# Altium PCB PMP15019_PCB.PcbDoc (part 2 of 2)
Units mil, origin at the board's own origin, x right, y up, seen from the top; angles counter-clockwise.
Board outline 3000 x 2000 mil, 6 copper layers (Top Layer, Signal Layer 1, Signal Layer 2, Signal Layer 3, Signal Layer 4, Bottom Layer), stack 61.6 mil thick; 82 components, 32 nets, 164 pads, 220 vias.
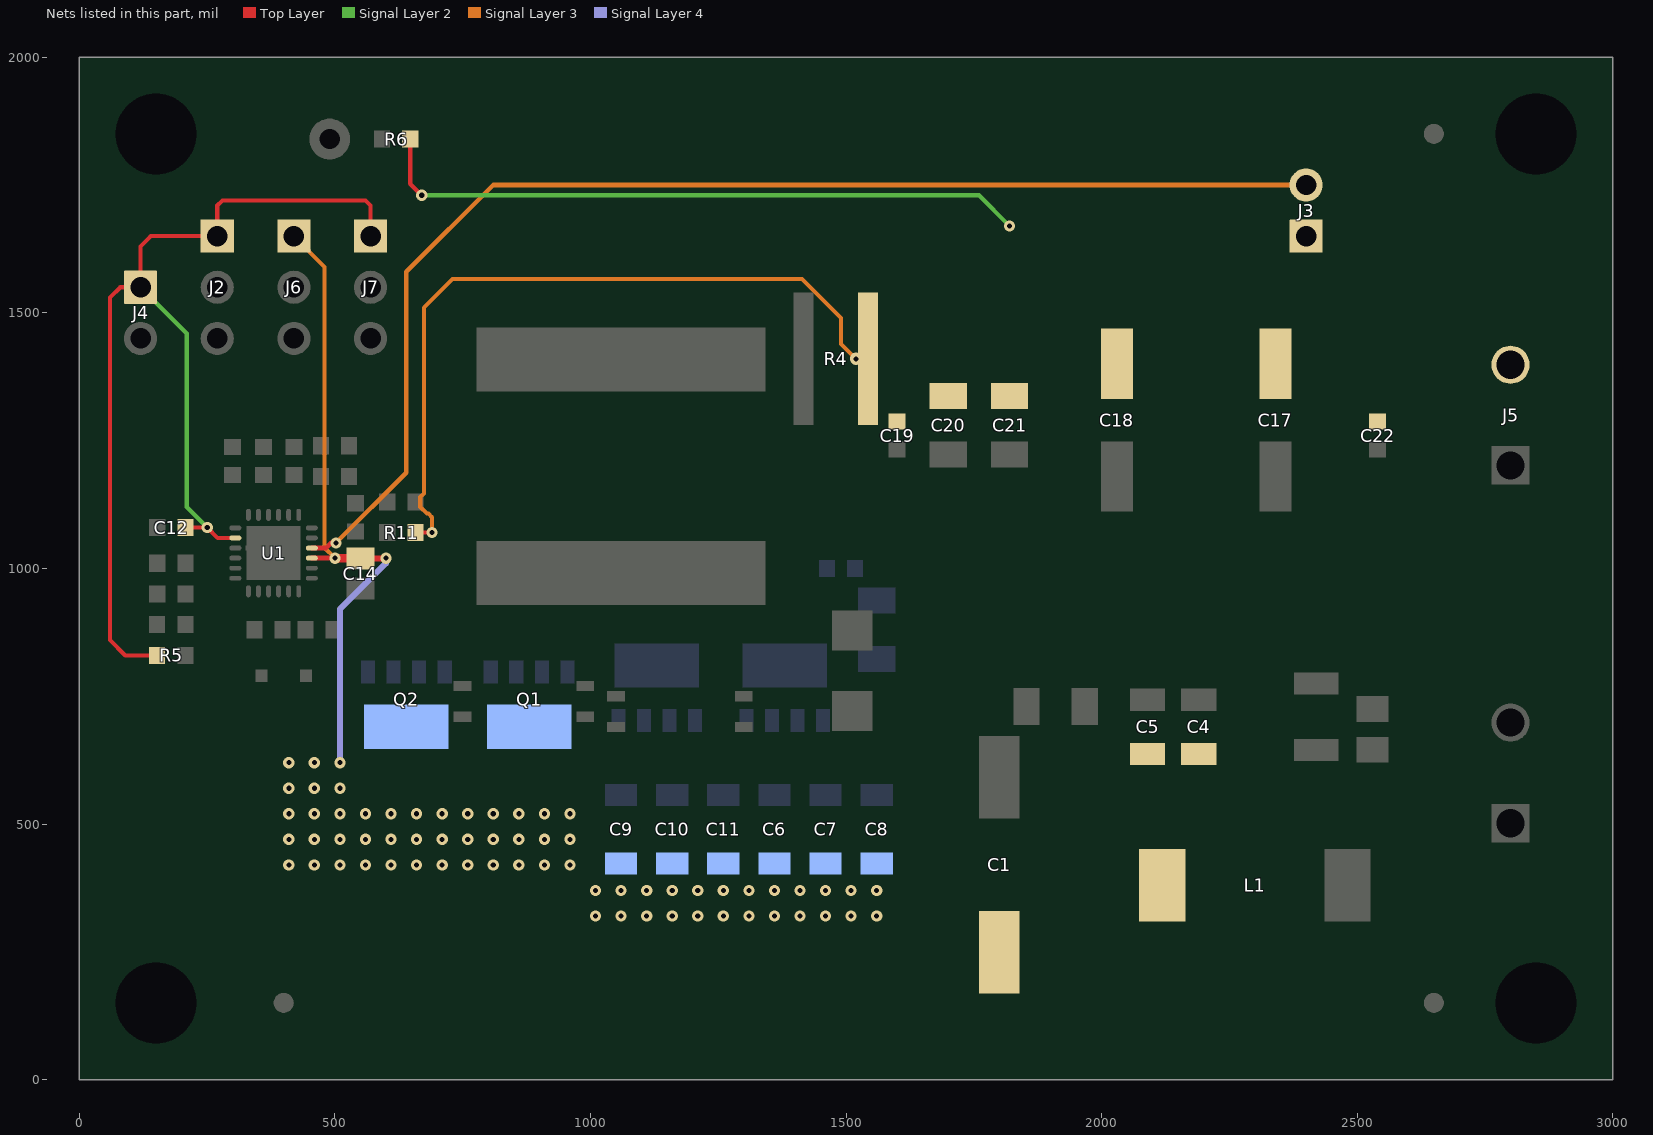
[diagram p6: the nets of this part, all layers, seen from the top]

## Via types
v1: diameter 22, hole 10, Top Layer to Bottom Layer, tented both sides, 199 vias
v2: diameter 22, hole 10, Top Layer to Bottom Layer, 14 vias
v3: diameter 19.68, hole 7.87, Top Layer to Bottom Layer, 5 vias
v4: diameter 24, hole 10, Top Layer to Bottom Layer, tented both sides, 2 vias

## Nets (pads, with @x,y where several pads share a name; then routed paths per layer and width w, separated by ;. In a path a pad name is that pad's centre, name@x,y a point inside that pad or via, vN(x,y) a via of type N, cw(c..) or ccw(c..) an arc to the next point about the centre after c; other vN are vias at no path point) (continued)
VCCX: J3.2 U1.16 | length 2469.2
  Top Layer w9: U1.16@454.96,1039.84 483.16,1039.84 493.31,1050 500.16,1050 500.28,1049.87 v2(502.38,1049.87)
  Signal Layer 3 w9: v2(502.38,1049.87) 640,1187.49 640,1580 810,1750 J3.2@2400,1750
VDDA: C12.2 J2.1 J4.1 J7.1 R5.1 U1.2 | length 2133.6
  Top Layer w8: J4.1@110,1560 120,1570 120,1630 140,1650 J2.1@270,1650 270,1710 280,1720 560,1720 570,1710 J7.1@570,1650 ; J4.1@120,1550 80.32,1550 60.32,1530 60.32,859.68 90,830 R5.1@152.44,830 ; C12.2@207.72,1080 v2(250.47,1080) 270.94,1059.53 U1.2@305.35,1059.53
  Signal Layer 2 w8: J4.1@120,1550 210.32,1459.68 210.32,1120.16 v2(250.47,1080)
VIN: C1.1 C4.1 C5.1 C6.1 C7.1 C8.1 C9.1 C10.1 C11.1 C14.2 J6.1 L1.2 Q1.5 Q2.5 U1.15 | length 1245.6
  Top Layer w10: U1.15@454.96,1020.16 v2@500,1020.16
  Top Layer w12: C14.2@550.16,1019.53 599.53,1019.53 v1(600,1020)
  Top Layer w16: v2(500.16,1020) C14.2@549.68,1020
  Signal Layer 3 w8: J6.1@420,1650 480,1590 480,1060.34 479.51,1059.84 479.51,1040.4 499.91,1020 v2(500.16,1020)
  Signal Layer 4 w12: v1(510,620) 510,920 600,1010 v1(600,1020)
  other v1: 1010,320 1060,320 1110,320 1160,320 1210,320 1260,320 1310,320 1360,320 1410,320 1460,320 1510,320 1560,320 1010,370 1060,370 1110,370 1160,370 1210,370 1260,370 1310,370 1360,370 1410,370 1460,370 1510,370 1560,370 410,420 460,420 510,420 560,420 610,420 660,420 710,420 760,420 810,420 860,420 910,420 960,420 410,470 460,470 510,470 560,470 610,470 660,470 710,470 760,470 810,470 860,470 910,470 960,470 410,520 460,520 510,520 560,520 610,520 660,520 710,520 760,520 810,520 860,520 910,520 960,520 410,570 460,570 510,570 410,620 460,620
VOUT: C17.1 C18.1 C19.1 C20.1 C21.1 C22.1 J3.1 J5.2 R4.2 R6.1 R11.2 | length 2742.8
  Top Layer w8: R6.1@647.56,1840 647.56,1752.44 v1(670,1730) ; R11.2@657.72,1070 v1(690,1070)
  Signal Layer 2 w8: v1(670,1730) 1760,1730 v1(1820,1670)
  Signal Layer 3 w8: v1(690,1070) 690,1100 682.87,1107.13 680.53,1107.13 667.13,1120.53 667.13,1139.47 668.13,1140.47 668.13,1140.75 674.13,1146.75 674.13,1510 730,1565.87 1414.13,1565.87 1490,1490 1490,1439.39 v4(1519.39,1410)
pads on no net: FID1.1 FID2.1 FID3.1 MH1.1 MH2.1 MH3.1 MH4.1

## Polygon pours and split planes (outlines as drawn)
AGND on Top Layer "Top Layer-No Net" (solid, pour order 174): 250.16,860 70.32,860 70.31,1490 650.32,1490 650.31,1139.76 250.16,1139.76
NetC2_1 on Top Layer "Top Layer-NetC2-1" (solid, pour order 172): 2932.8,302.8 2690,302.8 2570,182.8 2350,182.8 2350,645.12 2377.69,672.8 2600,672.8 2670,602.8 2680,592.8 2927.2,592.8 2980,540 2980,350
VIN on Top Layer "Top Layer-VIN" (solid, pour order 177): 2210,160 520,160 480,200 480,270 450,300 70,300 50,320 50,720 70,740 950.03,740 980,710.03 980,540 1015.43,504.57 1890.79,504.57 1911.18,524.96 1911.18,670 2076.61,670 2220,670 2260,630 2260,210
NetL2_2 on Top Layer "Top Layer-Net L2-2" (solid, pour order 173): 1450,1280 770,1280 770,1680 1450,1680
VOUT on Top Layer "Top Layer-Vout" (solid, pour order 176): 2992.3,1340 2717.32,1340 2700,1340 2630,1270 1510,1270 1510,1690 2996.38,1690
PGND on Top Layer "Top Layer-PGND" (solid, pour order 178): 3000,0 10,0 0,10 0,2000 3000,2000
NetC15_2 on Top Layer "Top Layer-C12-2" (solid, pour order 175): 541.57,770 540,771.57 540,850 650,960 695.58,960 752.91,1017.33 752.91,1062.91 790,1100 1390.49,1099.54 1410,1080 1480,1010 1480,770
VIN on Bottom Layer "Bottom Layer-Vin" (solid, pour order 188): 80,740 958.35,740 977.44,720.92 977.44,539.38 1012.25,504.57 1575.43,504.57 1599.37,480.63 1599.37,209.37 1570,180 350,180 320,210 320,270 290,300 80,300 50,330 50,710
NetC15_2 on Bottom Layer "Bottom Layer-C12-2" (solid, pour order 187): 541.57,770 540,771.57 540,850 650,960 700,960 752.91,1012.91 752.91,1062.91 790,1100 1390,1100 1480,1010 1480,770
PGND on Bottom Layer "Bottom Layer-PGND" (solid, pour order 189): 0,0 0,2000 3000,2000 3000,0
PGND on Signal Layer 1 "Signal Layer 1-PGND" (solid, pour order 179): 0,0 0,2000 3000,2000 3000,0
PGND on Signal Layer 4 "Signal Layer4 -PGND" (solid, pour order 186): 0,0 0,2000 3000,2000 3000,0
VIN on Signal Layer 2 "Bottom Layer-Vin" (solid, pour order 181): 90,640 941.81,640 977.44,604.38 977.44,542.56 1015.43,504.57 1578.74,504.57 1599.37,483.94 1599.37,209.37 1570,180 350,180 320,210 320,270 290,300 80,300 50,330 50,600
NetC15_2 on Signal Layer 2 "Top Layer-C12-2" (solid, pour order 180): 560,800 560,868.61 650.24,958.86 695.82,958.86 753.16,1016.19 753.16,1061.77 790.24,1098.86 1390.73,1098.39 1410.24,1078.86 1480.24,1008.86 1480.24,789.09 570.91,789.09
PGND on Signal Layer 2 "Top Layer-No Net1" (solid, pour order 182): 0,0 0,2000 3000,2000 3000,0
VIN on Signal Layer 3 "Bottom Layer-Vin" (solid, pour order 184): 70,640 943.78,640 977.44,606.34 977.44,524.96 997.83,504.57 1565.43,504.57 1599.37,470.63 1599.37,209.37 1570,180 345.85,180 320,205.85 320,279.61 299.61,300 70,300 50,320 50,620
NetC15_2 on Signal Layer 3 "Top Layer-C12-2" (solid, pour order 183): 565,795 565,870.58 654.42,960 700,960 757.33,1017.33 757.33,1062.91 794.42,1100 1394.9,1099.54 1414.42,1080 1484.42,1010 1484.42,770 590,770
PGND on Signal Layer 3 "Top Layer-No Net2" (solid, pour order 185): 0,0 0,2000 3000,2000 3000,0

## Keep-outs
Keep-Out Layer:
  the board outline again, w7
  text ".Layer_Name" at 577,-858.49 h60

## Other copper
Top Layer:
  rectangle net NetC15_2: 1462.67,835.59 1560,927.22
  pour cut-out: 1457.21,1270 1457.21,1690 1499.8,1690 1499.8,1270
  pour cut-out: 3000,940 2670,940 2670,970 3000,970
  pour cut-out: 2240,700 2364.88,700 2364.88,581.82 2430,516.71 2430,200 2480,150 2120,150 2170,200 2170,506.13 2240,576.13
  pour cut-out: 1367.09,1270 1367.09,1110 785.58,1110 752.91,1077.33 752.91,1270
  pour cut-out: 2240,660 1849.37,660 1849.37,690 2220,690 2240,690 2240,670
  pour cut-out: 1900.99,514.76 1849.37,514.76 1849.37,660 1930,660 1900,630
  pour cut-out: 2932.8,278.33 2998.33,278.33 ccw(c2998.33,280) 3000,280 3000,350
  pour cut-out: 2927.2,617.28 2994.44,617.28 ccw(c2994.44,619.68) 2996.85,619.68 2996.85,550
  text ".Layer_Name" at 577,-858.49 h60
Signal Layer 1:
  pour cut-out: 2077.56,639.13 3000,639.13 3000,260 2720,260 2580,120 2077.56,120
  pour cut-out: 2860,698.47 cw(c2804.66,693.82) 2809.32,638.47 2789.32,638.47 cw(c2794.66,693.13) 2740,698.47 cw(c2794.66,703.82) 2789.32,758.47 2809.32,758.47 cw(c2804.66,703.13)
  text ".Layer_Name" at 577,-858.49 h60
Signal Layer 2:
  pour cut-out: 2077.56,640 3000,640 3000,260 2710,260 2570,120 2077.56,120
  pour cut-out: 2860,698.47 cw(c2804.66,693.82) 2809.32,638.47 2789.32,638.47 cw(c2795.87,694.61) 2739.74,701.17 cw(c2793.18,705.03) 2789.32,758.47 2809.32,758.47 cw(c2804.66,703.13)
  text ".Layer_Name" at 577,-858.49 h60
Signal Layer 3:
  pour cut-out: 2080,650 3000,650 3000,260 2720,260 2580,120 2080,120
  pour cut-out: 2860,698.47 cw(c2804.66,693.82) 2809.32,638.47 2789.32,638.47 cw(c2794.38,693.41) 2739.45,698.47 cw(c2794.38,703.54) 2789.32,758.47 2809.32,758.47 cw(c2804.66,703.13)
  text ".Layer_Name" at 577,-858.49 h60
Signal Layer 4:
  pour cut-out: 2077.56,650 3000,650 3000,260 2710,260 2570,120 2077.56,120
  pour cut-out: 2860,698.47 cw(c2804.66,693.82) 2809.32,638.47 2789.32,638.47 cw(c2794.36,693.43) 2739.41,698.47 cw(c2794.36,703.52) 2789.32,758.47 2809.32,758.47 cw(c2804.66,703.13)
  text ".Layer_Name" at 577,-858.49 h60
Bottom Layer:
  pour cut-out: 2080,650 3000,650 3000,264.21 2714.2,264.21 2570,120 2080,120
  pour cut-out: 2860,698.47 cw(c2804.66,693.82) 2809.32,638.47 2789.32,638.47 cw(c2794.66,693.13) 2740,698.47 cw(c2794.66,703.82) 2789.32,758.47 2809.32,758.47 cw(c2804.66,703.13)
  text ".Layer_Name" at 577,-858.49 h60

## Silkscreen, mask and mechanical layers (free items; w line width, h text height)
Top Overlay:
  region: 2540,150 2240,150 2240,50 2540,50
  lines w7: 290,800 340,850 ; 566.93,1156.93 576.85,1156.93 566.89,1166.89 566.89,1156.89 590,1180 590,1210 620,1240 ; 340,850 340,840 330,850 340,850
  text "+" at 2940,1560 h100 r90
  text "VOUT" at 2570,1480 h60 r90
  text "-" at 2940,1010 h100 r90
  text "-" at 2940,830 h100 r90
  text "+" at 2940,320 h100 r90
  text "VIN" at 2630,230 h60 r90
  text ".PRJ_Number" at 1550,70 h60
  text ".PCB_Rev" at 2060,70.01 h60
  text "-" at 2170,70.01 h60
  text ".Layer_Name" at 577,-858.49 h60
Bottom Overlay:
  text ".Layer_Name" at 577,-858.49 h60
Top Paste:
  text ".Layer_Name" at 577,-858.49 h60
Bottom Paste:
  text ".Layer_Name" at 577,-858.49 h60
Top Solder:
  text ".Layer_Name" at 577,-858.49 h60
  text ".Layer_Name" at 577,-858.49 h60
Bottom Solder:
  text ".Layer_Name" at 577,-858.49 h60
Drill Guide:
  text ".Layer_Name" at 577,-858.49 h60
M1 Board Outline:
  the board outline again, w10
  text ".Layer_Name" at 577,-858.49 h60
M2 Board Dimensions:
  rectangle: 125,-400 500,-275
  rectangle: 0,-275 125,-150
  lines w7: 0,-275 1000,-275 ; 125,-400 125,-150 ; 250,-400 250,-150 ; 500,-400 500,-150 ; 750,-400 750,-150 ; 0,-400 0,-150 1000,-150 1000,-400 0,-400
  text ".Layer_Name" at 577,-858.49 h60
M3 3D STEP Top:
  text ".Layer_Name" at 577,-858.49 h60
M4 3D STEP Bottom:
  text ".Layer_Name" at 577,-858.49 h60
M5 Assembly Top:
  lines w10: -292,-930.17 6308,-930.17 ; -292,-726.83 6310,-726.83 ; -292,-523.5 -292,-1133.5 3713,-1133.5 6310,-1133.5 6310,-523.5 -291.5,-523.5 -291.5,-1133.5 1284,-1133.5 ; 2173,-1133.5 2173,-523.5 ; 3440,-726.83 3440,-523.5 ; 4280,-726.83 4280,-523.5 ; 4902,-1140 4902,-937.17
  text "COMPONENTS MARKED 'DNP' SHOULD NOT BE POPULATED." at 1153.5,-318.5 h60
  text "ASSEMBLY VARIANT:" at 1153,-434 h60
  text ".VariantName" at 2189,-434 h60
  text "PCB VIEWED FROM TOP SIDE" at -228.5,-655.67 h60
  text "BOARD #:" at 2248,-655.67 h60
  text ".PRJ_Number" at 2793.5,-655.67 h60
  text "REV:" at 3638,-655.67 h60
  text ".PCB_Rev" at 3929.5,-655.67 h60
  text "SVN REV:" at 4476,-655.67 h60
  text ".VersionControl_RevNumber" at 4982,-655.67 h60
  text "TID #:" at 2248,-859 h60
  text ".TID" at 2793.5,-859 h60
  text "PLOT NAME =" at -228.5,-1064.34 h60
  text ".plot_File_Name" at 577,-1064.34 h60
  text "GENERATED    :" at 2250,-1064.34 h60
  text ".Print_Date" at 3119.5,-1064.34 h60
  text ".Print_Time" at 3848.5,-1064.34 h60
  text "TEXAS INSTRUMENTS" at 5113,-1064.34 h60
M6 Assembly Bottom:
  lines w10: -292.5,-727.33 6309.5,-727.33 ; -290.5,-930.67 6309.5,-930.67 ; 1115.5,-1140.5 1115.5,-937.67 ; 1737.5,-727.33 1737.5,-524 ; 2577.5,-727.33 2577.5,-524 ; 3844.5,-1134 3844.5,-524 ; 4733.5,-1134 6309,-1134 6309,-524 -292.5,-524 -292.5,-1134 2304.5,-1134 6309.5,-1134 6309.5,-524
  text "COMPONENTS MARKED 'DNP' SHOULD NOT BE POPULATED." at 6102,-318 h60
  text ".VariantName" at 5058,-434 h60
  text "ASSEMBLY VARIANT:" at 6097,-434 h60
  text ".VersionControl_RevNumber" at 1035.5,-656.17 h60
  text "SVN REV:" at 1541.5,-656.17 h60
  text ".PCB_Rev" at 2088,-656.17 h60
  text "REV:" at 2379.5,-656.17 h60
  text ".PRJ_Number" at 3224,-656.17 h60
  text "BOARD #:" at 3769.5,-656.17 h60
  text "PCB VIEWED FROM BOTTOM SIDE" at 6246,-656.17 h60
  text ".TID" at 3224,-859.5 h60
  text "TID #:" at 3769.5,-859.5 h60
  text "TEXAS INSTRUMENTS" at 904.5,-1064.84 h60
  text ".Print_Time" at 2169,-1064.84 h60
  text ".Print_Date" at 2898,-1064.84 h60
  text "GENERATED    :" at 3767.5,-1064.84 h60
  text ".plot_File_Name" at 5440.5,-1064.84 h60
  text "PLOT NAME =" at 6246,-1064.84 h60
M9 Title Sheet:
  drawing of 57 lines, arcs and shapes, not listed
  text "1" at 739.84,8036.5 h70
  text "2" at 3235.5,8036.5 h70
  text "3" at 5724.84,8036.5 h70
  text "4" at 8231.51,8036.5 h70
  text "5" at 10730.5,8036.5 h70
  text "6" at 13235.5,8036.5 h70
  text "A" at -416.5,6893.5 h70
  text "A" at 14383.5,6893.5 h70
  text "B" at -416.5,4513.5 h70
  text "B" at 14383.5,4513.5 h70
  text "C" at -416.5,2138.5 h70
  text "C" at 14383.5,2138.5 h70
  text "PROJECT TITLE:" at 11343.5,277.5 h45
  text ".PRJ_Title" at 11393.5,144.17 h70
  text "DESIGNED FOR:" at 11343.5,-23.5 h45
  text ".PRJ_Customer" at 11393.5,-163.5 h70
  text "D" at -416.5,-231.5 h70
  text "D" at 14383.5,-231.5 h70
  text "FILE NAME:" at 11343.5,-323.5 h45
  text ".PCB_File_Name_No_Path" at 11393.5,-443.5 h70
  text "Texas Instruments (TI) and/or its licensors do not warrant the accuracy or completeness of this specification" at 6374,-605.34 h45
  text "ENGINEER:" at 11343.5,-613.5 h45
  text "LAYOUT BY:" at 12848.5,-613.5 h45
  text "or any information contained therein. TI and/or its licensors do not warrant that this design will meet" at 6329.01,-718 h45
  text ".PRJ_Engineer" at 11393.5,-768.49 h70
  text ".PCB_Layout" at 12899,-768.49 h70
  text "the specifications, will be suitable for your application or fit for any particular purpose, or will operate in" at 6329.01,-830.67 h45
  text ".Layer_Name" at 577,-858.49 h60
  text "ALTIUM DESIGNER VERSION:" at 12848.5,-923.5 h45
  text "an implementation. TI and/or its licensors do not warrant that the design is production worthy. You should" at 6329.01,-943.33 h45
  text "completely validate and test your design implementation to confirm the system functionality for your application." at 6374,-1056 h45
  text ".print_Scale" at 11393.5,-1056.83 h70
  text ".Application_BuildNumber" at 12899,-1056.83 h70
  text "1" at 739.84,-1263.5 h70
  text "2" at 3235.5,-1263.5 h70
  text "3" at 5724.84,-1263.5 h70
  text "4" at 8231.51,-1263.5 h70
  text "5" at 10730.5,-1263.5 h70
  text "6" at 13235.5,-1263.5 h70
M10 Fab Notes:
  drawing of 173 lines, arcs and shapes, not listed
  text "DESIGN INFORMATION" at 12377.02,6201 h60
  text "MIN. TRACK WIDTH:" at 11732.46,6021 h60
  text "8" at 12828.7,6021 h60
  text "MIL" at 12983.46,6021 h60
  text "MIN. CLEARANCE:" at 11732.46,5889 h60
  text "0.2" at 12768.7,5889 h60
  text "mm" at 12983.46,5889 h60
  text "MIN. VIA PAD SIZE:" at 11732.46,5757 h60
  text "24" at 12798.71,5757 h60
  text "MIL" at 12983.46,5757 h60
  text "0.05mm (2MIL)" at 12427.46,5615.29 h60
  text "MINIMUM ANNULAR RING" at 11403.23,5611 h60
  text "EXTERNAL" at 13135.46,5611 h60
  text "PER" at 11603.23,5493 h60
  text "IPC-D-275 CLASS 2 LEVEL C" at 11823.23,5493 h60
  text "MIL, HOLES" at 13311.46,5380.71 h60
  text "+/-" at 12919,5380 h60
  text "+/-" at 13773,5380 h60
  text "REGISTRATION TOLERANCES:" at 11403.23,5375 h60
  text "METAL" at 12603,5375 h60
  text "5" at 13179.2,5375 h60
  text "3" at 14012.2,5375 h60
  text "MIL" at 14128.46,5375 h60
  text "+/-" at 13773,5262 h60
  text "HOLE SIZE TOLERANCE (UNLESS OTHERWISE SPECIFIED):" at 11403.23,5257 h60
  text "3" at 14012.2,5257 h60
  text "MIL" at 14128.46,5257 h60
  text "MATERIAL:" at 11328.46,5047.54 h60
  text "FR-4 High Tg" at 12314.9,4907.21 h60
  text "FR-408" at 11749.46,4898.64 h60
  text "OTHER" at 13237.46,4898.64 h60
  text "X" at 12160,4895 h60
  text "62 MIL (1.6mm) +/-10%" at 12069.56,4735.92 h60
  text "THICKNESS:" at 11403.23,4731.64 h60
  text "X" at 11941.4,4731.64 h60
  text "OTHER" at 13354.46,4731.64 h60
  text "TOLERANCE:" at 11403.23,4573.64 h60
  text "X" at 12242.53,4573.64 h60
  text "ANSI IPC-6012 TYPE 3 CLASS 2" at 12429.48,4573.64 h60
  text "OTHER +/-" at 12429.46,4417.64 h60
  text "BOW & TWIST:" at 11403.23,4260.64 h60
  text "X" at 12242.53,4260.64 h60
  text "ANSI IPC-6012 TYPE 3 CLASS 2" at 12429.48,4260.64 h60
  text "OTHER +/-" at 12429.46,4102.13 h60
  text "DRILLING:" at 11328.46,3963.64 h60
  text "REFERENCE:" at 11403.23,3846.64 h60
  text "X" at 12051.46,3846.64 h60
  text "AS SHOWN" at 12238.46,3846.64 h60
  text "X" at 12952.46,3846.64 h60
  text "NC_DRILL FILES" at 13089.46,3846.64 h60
  text "PTH COPPER THICKNESS:" at 11403.23,3688.64 h60
  text "X" at 12533.46,3688.64 h60
  text "20-30 um" at 12670.46,3688.64 h60
  text "OTHER" at 13387.46,3688.64 h60
  text "BOARD FINISH:" at 11328.46,3529.64 h60
  text "SILKSCREEN:" at 11483.68,3411.64 h60
  text "X" at 12432.46,3411.64 h60
  text "TOP" at 12558.46,3411.64 h60
  text "X" at 12942.46,3411.64 h60
  text "BOTTOM" at 13069.46,3411.64 h60
  text "SILKSCREEN COLOR:" at 11483.68,3244.64 h60
  text "X" at 12431.42,3244.64 h60
  text "WHITE" at 12558.46,3244.64 h60
  text "OTHER" at 13069.46,3244.64 h60
  text "X" at 12562.42,3085.44 h60
  text "GREEN" at 12689.46,3085.44 h60
  text "OTHER" at 13307.46,3085.44 h60
  text "SOLDER RESIST COLOR:" at 11483.68,3074.64 h60
  text "X" at 12562.42,2915.44 h60
  text "MATTE" at 12689.46,2915.44 h60
  text "SEMI-GLOSS" at 13307,2914.8 h60
  text "IMMERSION GOLD (ENIG)" at 12389.46,2726.92 h60
  text "ENEPIG" at 13727,2723.64 h60
  text "SURFACE FINISH:" at 11328.46,2722.64 h60
  text "X" at 12202.51,2722.64 h60
  text "IMM. TIN/SILVER OR EQUIV" at 11658,2565.64 h60
  text "OTHER" at 13089.46,2565.64 h60
  text "X" at 12200,2390 h60
  text "ARRAY/PANEL:" at 11328.46,2386.64 h60
  text "CUT AND TRIM PER M1 BOARD OUTLINE" at 12389.46,2382.35 h60
  text "N.C. ROUTE" at 12389.46,2230.64 h60
  text "V. SCORE" at 13255.46,2230.64 h60
  text "CERTIFICATION:" at 11328.46,2093.64 h60
  text "MATERIALS AND WORKMANSHIP FOR ALL PCBS" at 12053.46,2093.64 h60
  text "TO MEET OR EXCEED THE REQUIREMENTS OF:" at 12053.46,1995.64 h60
  text "X" at 11679.96,1859.13 h60
  text "ANSI IPC-A-600F CLASS ->" at 11818.96,1859.13 h60
  text "X" at 13458.02,1859.13 h60
  text "2" at 13576.96,1859.14 h60
  text "1" at 13261.96,1857.64 h60
  text "3" at 13930.96,1857.64 h60
  text "X" at 12494.02,1699.64 h60
  text "RoHS" at 12630.96,1699.64 h60
  text "OTHER" at 13275.36,1699.64 h60
  text "PER ORDER" at 13672.42,1699.64 h60
  text "ALL BOARDS MUST MEET OR EXCEED UL94-V0 REQUIREMENTS." at 11356,1534 h60
  text "PCB MUST BEAR THE UL94V-0 UL REGISTERED MATERIAL ID NUMBER" at 11356,1414 h60
  text "ADDITIONAL REQUIREMENTS:" at 11328.46,1240.64 h60
  text "MICROSECTION:" at 11403.23,1125.64 h60
  text "YES" at 12308.96,1125.64 h60
  text "REQUIRED" at 13170.46,969.49 h60
  text "BARE BOARD ELEC. TEST:" at 11403.23,966.64 h60
  text "NONE" at 12708.96,966.64 h60
  text "X" at 13043.46,966.64 h60
  text "PER ORDER" at 13762.46,966.64 h60
  text ".Layer_Name" at 577,-858.49 h60
M11 Gerber Information:
  lines w10: -292,-930.17 6308,-930.17 ; -292,-726.83 6310,-726.83 ; -292,-523.5 -292,-1133.5 3713,-1133.5 6310,-1133.5 6310,-523.5 -291.5,-523.5 -291.5,-1133.5 1284,-1133.5 ; 2173,-1133.5 2173,-523.5 ; 3440,-726.83 3440,-523.5 ; 4280,-726.83 4280,-523.5 ; 4902,-1140 4902,-937.17
  text "ALL ARTWORK VIEWED FROM TOP SIDE" at -228.5,-655.67 h60
  text "BOARD #:" at 2248,-655.67 h60
  text ".PRJ_Number" at 2793.5,-655.67 h60
  text "REV:" at 3638,-655.67 h60
  text ".PCB_Rev" at 3929.5,-655.67 h60
  text "SVN REV:" at 4476,-655.67 h60
  text ".VersionControl_RevNumber" at 4982,-655.67 h60
  text "LAYER NAME =" at -228.5,-858.49 h60
  text "TID #:" at 2248,-859 h60
  text ".TID" at 2793.5,-859 h60
  text "PLOT NAME =" at -228.5,-1064.34 h60
  text ".plot_File_Name" at 577,-1064.34 h60
  text "GENERATED    :" at 2250,-1064.34 h60
  text ".Print_Date" at 3119.5,-1064.34 h60
  text ".Print_Time" at 3848.5,-1064.34 h60
  text "TEXAS INSTRUMENTS" at 5113,-1064.34 h60
M12 Stackup:
  drawing of 399 lines, arcs and shapes, not listed
  text "Layer" at 6790.74,7870 h60
  text "Name" at 7200.66,7870 h60
  text "Material" at 8140.4,7870 h60
  text "Thickness" at 9000.16,7870 h60
  text "Constant" at 9650,7870 h60
  text "Board Layer Stack" at 10219.86,7870 h60
  text "1" at 6790.74,7750 h60
  text "Top Overlay" at 7200.66,7750 h60
  text "2" at 6790.74,7630 h60
  text "Top Solder" at 7200.66,7630 h60
  text "Solder Resist" at 8140.4,7630 h60
  text "0.40mil" at 9000.16,7630 h60
  text "3.5" at 9650,7630 h60
  text "3" at 6790.74,7510 h60
  text "Top Layer" at 7200.66,7510 h60
  text "Copper" at 8140.4,7510 h60
  text "4.20mil" at 9000.16,7510 h60
  text "4" at 6790.74,7390 h60
  text "Dielectric1" at 7200.66,7390 h60
  text "FR-4" at 8140.4,7390 h60
  text "5.00mil" at 9000.16,7390 h60
  text "4.8" at 9650,7390 h60
  text "5" at 6790.74,7270 h60
  text "Signal Layer 1" at 7200.66,7270 h60
  text "Copper" at 8140.4,7270 h60
  text "2.80mil" at 9000.16,7270 h60
  text "6" at 6790.74,7150 h60
  text "Dielectric 3" at 7200.66,7150 h60
  text "5.00mil" at 9000.16,7150 h60
  text "4.2" at 9650,7150 h60
  text "7" at 6790.74,7030 h60
  text "Signal Layer 2" at 7200.66,7030 h60
  text "Copper" at 8140.4,7030 h60
  text "2.80mil" at 9000.16,7030 h60
  text "8" at 6790.74,6910 h60
  text "Dielectric 4" at 7200.66,6910 h60
  text "22.00mil" at 9000.16,6910 h60
  text "4.2" at 9650,6910 h60
  text "9" at 6790.74,6790 h60
  text "Signal Layer 3" at 7200.66,6790 h60
  text "Copper" at 8140.4,6790 h60
  text "2.80mil" at 9000.16,6790 h60
  text "10" at 6790.74,6670 h60
  text "Dielectric 5" at 7200.66,6670 h60
  text "5.00mil" at 9000.16,6670 h60
  text "4.2" at 9650,6670 h60
  text "11" at 6790.74,6550 h60
  text "Signal Layer 4" at 7200.66,6550 h60
  text "Copper" at 8140.4,6550 h60
  text "2.80mil" at 9000.16,6550 h60
  text "12" at 6790.74,6430 h60
  text "Dielectric 2" at 7200.66,6430 h60
  text "5.00mil" at 9000.16,6430 h60
  text "4.2" at 9650,6430 h60
  text "13" at 6790.74,6310 h60
  text "Bottom Layer" at 7200.66,6310 h60
  text "Copper" at 8140.4,6310 h60
  text "4.20mil" at 9000.16,6310 h60
  text "14" at 6790.74,6190 h60
  text "Bottom Solder" at 7200.66,6190 h60
  text "Solder Resist" at 8140.4,6190 h60
  text "0.40mil" at 9000.16,6190 h60
  text "3.5" at 9650,6190 h60
  text "15" at 6790.74,6070 h60
  text "Bottom Overlay" at 7200.66,6070 h60
  text ".Layer_Name" at 577,-858.49 h60
M13 Component Bodies Top:
  text ".Layer_Name" at 577,-858.49 h60
M14 Component Bodies Bottom:
  text ".Layer_Name" at 577,-858.49 h60
M15 Courtyards Top:
  text ".Layer_Name" at 577,-858.49 h60
M16 Courtyards Bottom:
  text ".Layer_Name" at 577,-858.49 h60
Drill Drawing:
  lines w10: 5656.04,2755.99 5669.83,2755.99 5683.63,2742.2 5697.43,2755.99 5711.23,2755.99 5697.43,2769.79 5711.23,2783.59 5697.43,2783.59 5683.63,2797.39 5669.83,2783.59 5656.04,2783.59 5669.83,2769.79 5656.04,2755.99 ; 5656.04,2866.37 5683.63,2880.17 5711.23,2866.37 5697.43,2893.97 5711.23,2921.56 5683.63,2907.76 5656.04,2921.56 5669.83,2893.97 5656.04,2866.37 ; 5656.04,2990.55 5711.23,2990.55 5711.23,3045.74 5656.04,3045.74 5656.04,2990.55 ; 5656.04,3114.72 5656.04,3128.52 5669.83,3142.32 5656.04,3156.12 5656.04,3169.91 5669.83,3169.91 5683.63,3156.12 5697.43,3169.91 5711.23,3169.91 5711.23,3156.12 5697.43,3142.32 5711.23,3128.52 5711.23,3114.72 5697.43,3114.72 5683.63,3128.52 5669.83,3114.72 5656.04,3114.72 ; 5656.04,3294.09 5711.23,3294.09 5683.63,3238.9 5656.04,3294.09
  lines w12: 5606,2704.94 7583.93,2704.94 ; 5606,3325.82 7583.93,3325.82 ; 5943.86,2580.77 5943.86,3450 ; 6275.86,2580.77 6275.86,3450 ; 6912.42,2580.77 6912.42,3450 ; 7171.53,2580.77 7171.53,3450 ; 5606,2580.77 7583.93,2580.77 7583.93,3450 5606,3450 5606,2580.77
  text "Symbol" at 5680.51,3363.08 h72
  text "Quantity" at 5981.11,3363.08 h72
  text "Finished Hole Size" at 6313.12,3363.08 h72
  text "Plated" at 6949.67,3363.08 h72
  text "Hole Type" at 7208.78,3363.08 h72
  text "4" at 5981.11,3238.9 h60
  text "159.00mil (4.039mm)" at 6313.12,3238.9 h60
  text "NPTH" at 6949.67,3238.9 h60
  text "Round" at 7208.78,3238.9 h60
  text "5" at 5981.11,3114.72 h60
  text "7.87mil (0.200mm)" at 6313.12,3114.72 h60
  text "PTH" at 6949.67,3114.72 h60
  text "Round" at 7208.78,3114.72 h60
  text "215" at 5981.11,2990.55 h60
  text "10.00mil (0.254mm)" at 6313.12,2990.55 h60
  text "PTH" at 6949.67,2990.55 h60
  text "Round" at 7208.78,2990.55 h60
  text "14" at 5981.11,2866.37 h60
  text "40.00mil (1.016mm)" at 6313.12,2866.37 h60
  text "PTH" at 6949.67,2866.37 h60
  text "Round" at 7208.78,2866.37 h60
  text "4" at 5981.11,2742.2 h60
  text "55.12mil (1.400mm)" at 6313.12,2742.2 h60
  text "PTH" at 6949.67,2742.2 h60
  text "Round" at 7208.78,2742.2 h60
  text "242 Total" at 5981.11,2618.02 h60
  text ".Layer_Name" at 577,-858.49 h60

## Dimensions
0,0 to 0,2000 on M2 Board Dimensions
0,0 to 3000,0 on M2 Board Dimensions
0,-400 to 1000,-400 on M2 Board Dimensions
